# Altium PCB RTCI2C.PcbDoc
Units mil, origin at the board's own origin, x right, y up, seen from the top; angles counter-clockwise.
Board outline 1000 x 1125 mil, 2 copper layers (Top Layer, Bottom Layer), stack 61.855 mil thick; 14 components, 17 nets, 53 pads, 36 vias.
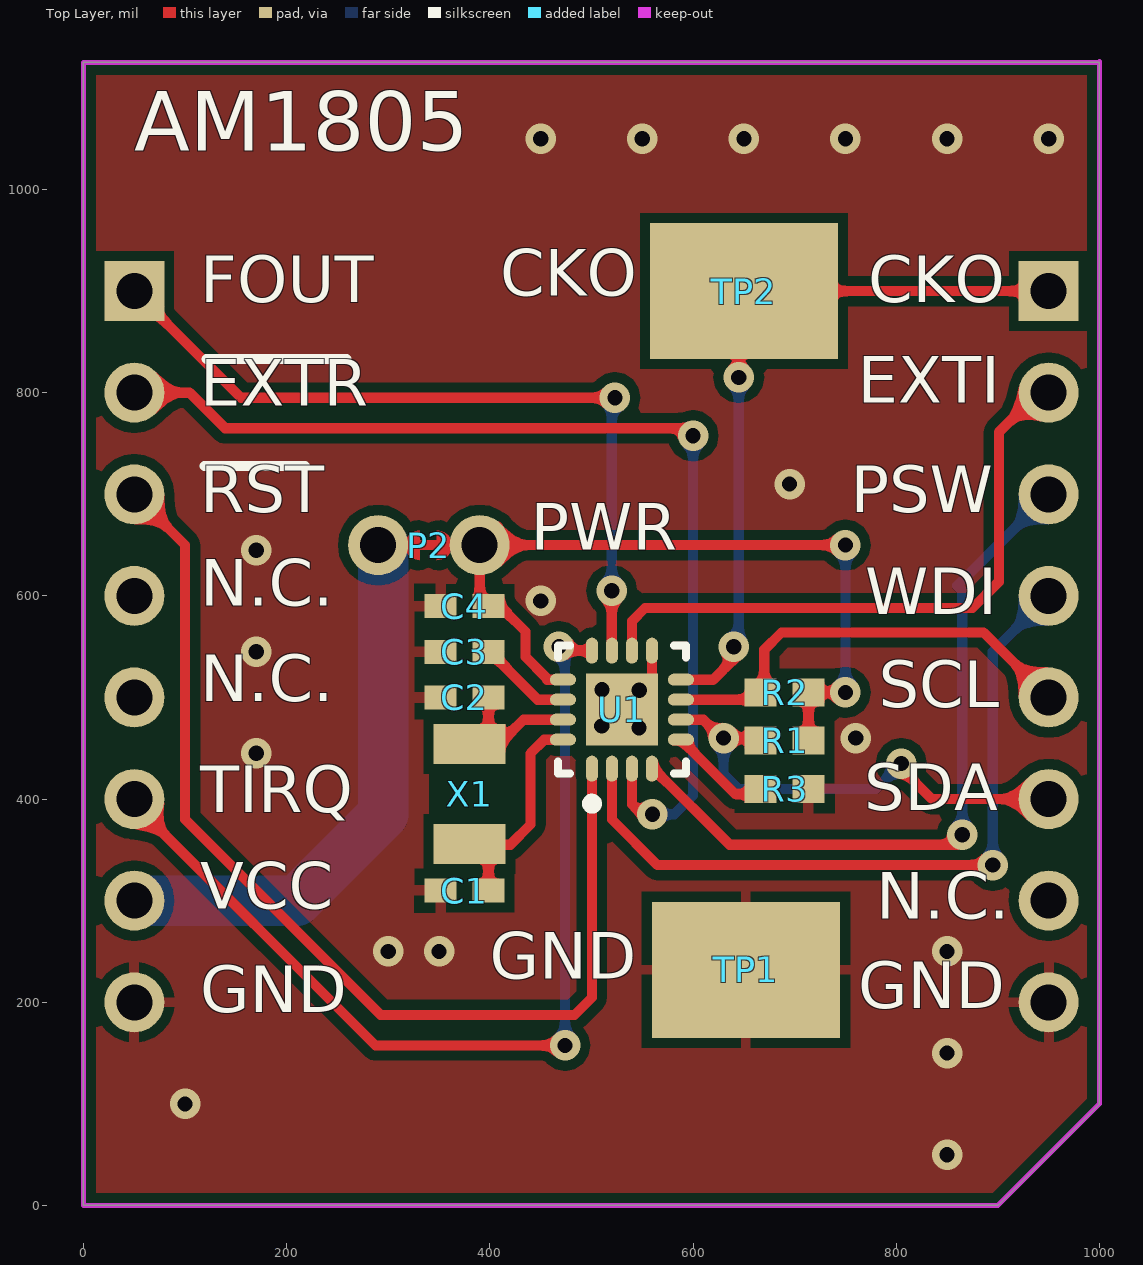
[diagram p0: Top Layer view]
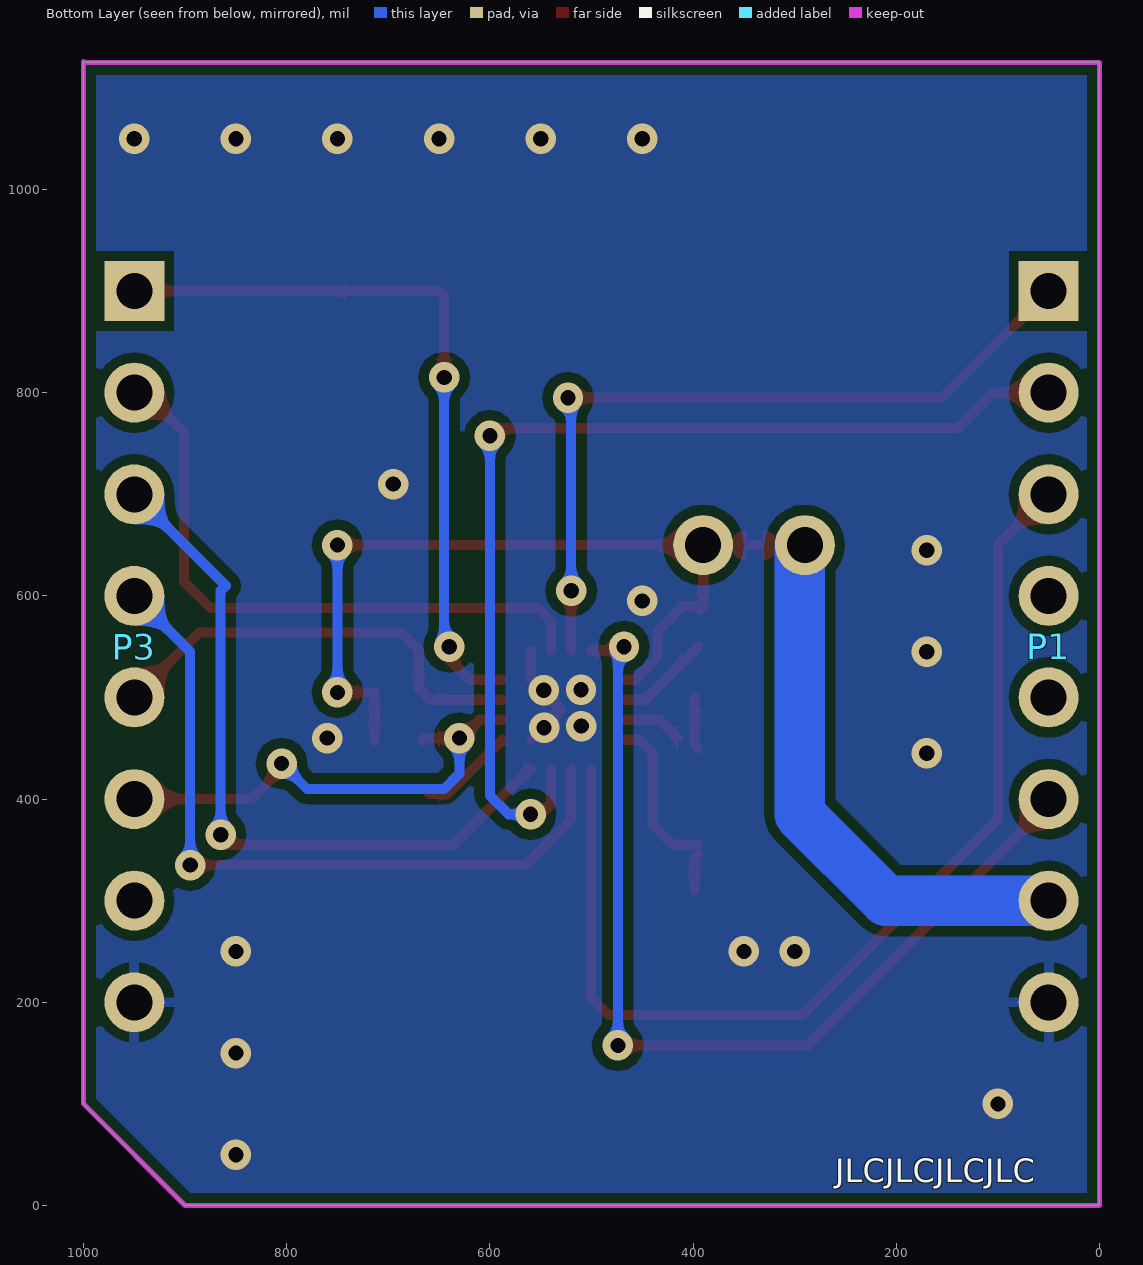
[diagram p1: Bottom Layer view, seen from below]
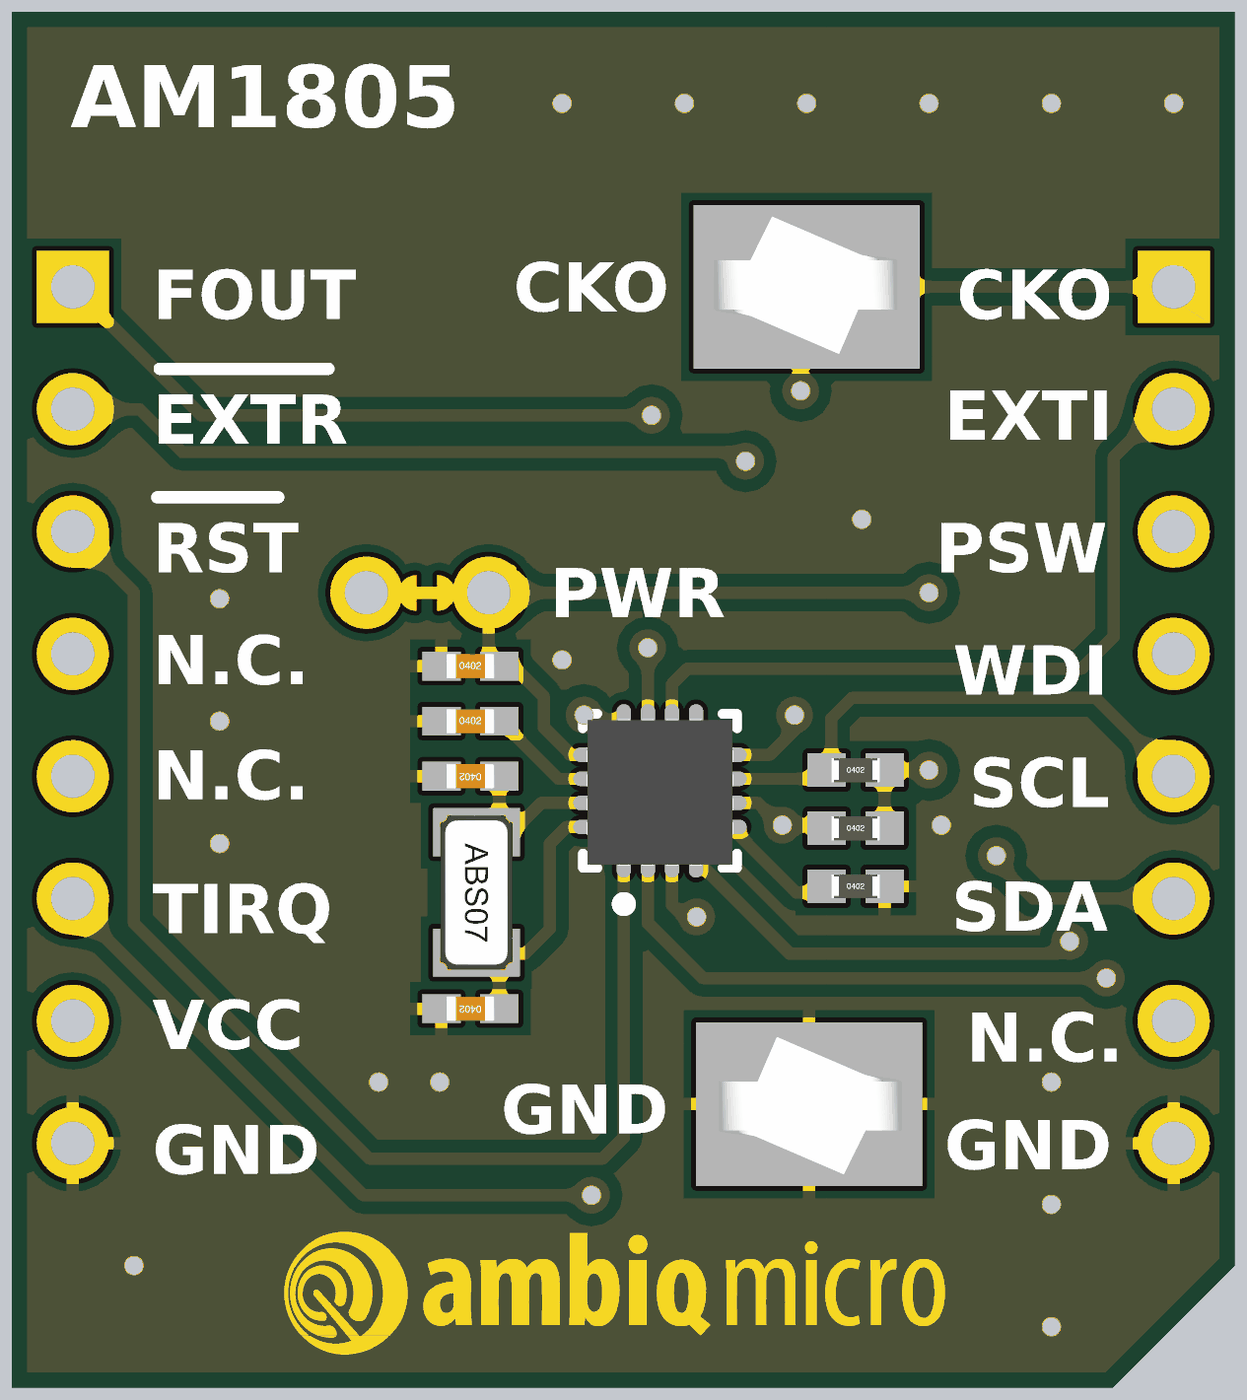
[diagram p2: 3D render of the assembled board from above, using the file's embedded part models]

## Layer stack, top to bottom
Top Solder: solder mask 0.4, Solder Resist, Dk 3.5
Top Layer: signal copper 1.4
Dielectric 1: dielectric 59.0551, FR-4, Dk 4.8
Bottom Layer: signal copper 1.4
Bottom Solder: solder mask 0.4, Solder Resist, Dk 3.5

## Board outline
0,0 900,0 1000,100 1000,1125 0,1125

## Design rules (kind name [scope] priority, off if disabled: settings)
Clearance [All] p1: gap=10 ignorepadtopadclearanceinfootprint=TRUE except(0: Arc-Hole Track-Hole SMDPad-Hole THPad-Hole Via-Hole Fill-Hole Poly-Hole Region-Hole Text-Hole; 8: Arc-Arc Arc-Track Arc-SMDPad Track-Track Track-SMDPad)
MinimumSolderMaskSliver [All] p1 off: minsoldermaskwidth=10
PolygonConnect PolygonConnect_1 [ISVIA] p1: connectstyle=Direct reliefconductorwidth=10 reliefentries=4 polygonreliefangle="90 Angle" airgapwidth=10
PolygonConnect [All] p2: connectstyle=Relief reliefconductorwidth=10 reliefentries=4 polygonreliefangle="90 Angle" airgapwidth=10
RoutingVias [All] p1: holewidth=15 width=30 viastyle="Through Hole" minholewidth=12 minwidth=24 maxholewidth=250 maxwidth=500
SilkToSolderMaskClearance [IsPad] p1 off: minsilkscreentomaskgap=10 clearancetoexposedcopper=TRUE
SolderMaskExpansion [All] p1: expansion=4
Width [All] p1: maxlimit=1000 minlimit=8 preferedwidth=10 minimp=50.000000 maximp=50.000000 favimp=50.000000
28 further rules are at their usual default settings.

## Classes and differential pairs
component class RTCI2C: C1 C2 C3 C4 P1 P2 P3 R1 R2 R3 TP1 TP2 U1

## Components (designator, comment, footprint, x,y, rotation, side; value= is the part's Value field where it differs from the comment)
C1 "1pF" CAPC1005N 375,310 r180 top
C2 "1pF" CAPC1005N 375,500 r180 top
C3 "47pF" CAPC1005N 375,545 r0 top
C4 "100nF" CAPC1005N 375,590 r0 top
P1 "Header 1X8" HEADER1X8 50,550 r270 bottom locked
P2 "SBS-HEADER" SBS-HEADER 340,650 r0 top net-tie
P3 "Header 1X8" HEADER1X8 950,550 r270 bottom locked
R1 "2K2" RESC1005N 690,457.5 r0 top
R2 "2K2" RESC1005N 690,505 r0 top
R3 "0R" RESC1005N 690,410 r0 top
TP1 "5016" 5016 652,232 r180 top
TP2 "5016" 5016 650,900 r0 top
U1 "AM1805" QFN50P300X300-16W4L 530,488 r90 top
X1 "ABS07W-32.768K" ABS07W 380,405 r270 top

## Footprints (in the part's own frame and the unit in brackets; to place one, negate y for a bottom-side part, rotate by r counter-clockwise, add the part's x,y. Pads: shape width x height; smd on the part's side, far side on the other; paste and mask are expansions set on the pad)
5016 [mm]
  rect 4.7x3.4 smd: 1(0,0)
  body extent -1.92,-1.4 1.89,1.46, height 2.3
ABS07W [mm]
  rect 1x1.8 smd: 1(-1.25,0) 2(1.25,0)
  body extent -1.61,-0.76 1.61,0.76, height 0.91
CAPC1005N [mm] "Chip Capacitor, Body 1.0x0.5mm, IPC Medium Density"
  rect 0.8x0.6 smd: 1(-0.6,0) 2(0.6,0)
  body extent -0.5,-0.26 0.5,0.26, height 0.51
HEADER1X8 [mm]
  rect 1.5x1.5 hole 0.9: 1(-8.89,0)
  round 1.5 hole 0.9: 2(-6.35,0) 3(-3.81,0) 4(-1.27,0) 5(1.27,0) 6(3.81,0) 7(6.35,0) 8(8.89,0)
  body extent -10.16,-1.27 10.16,1.27, height 8.38
QFN50P300X300-16W4L [mm] "QFN, 16-Leads, Body 3x3mm, Pitch 0.5mm, IPC High Density"
  oval 0.65x0.3 smd: 1(-1.475,0.75) 2(-1.475,0.25) 3(-1.475,-0.25) 4(-1.475,-0.75) 9(1.475,-0.75) 10(1.475,-0.25) 11(1.475,0.25) 12(1.475,0.75)
  oval 0.3x0.65 smd: 5(-0.75,-1.475) 6(-0.25,-1.475) 7(0.25,-1.475) 8(0.75,-1.475) 13(0.75,1.475) 14(0.25,1.475) 15(-0.25,1.475) 16(-0.75,1.475)
  rect 1.8x1.8 smd: 17(0,0)
  silkscreen extent -2.47,-1.6 1.6,1.6, body extent -1.55,-1.52 1.49,1.52, height 0.9
RESC1005N [mm] "Chip Resistor, Body 1.1x0.5mm, IPC Medium Density"
  rect 0.8x0.7 smd: 1(-0.6,0) 2(0.6,0)
  body extent -0.5,-0.25 0.5,0.25, height 0.3
SBS-HEADER [mm]
  round 1.5 hole 0.9: 1(-1.27,0) 2(1.27,0)
  Top Layer region: -0.225,-0.375 -0.388,-0.341 -0.52,-0.239 -0.594,-0.089 -0.594,0.078 -0.521,0.228 -0.389,0.33 -0.226,0.364 -0.226,0.364 -0.225,0.364
  Top Layer region: 0.2,0.364 0.363,0.33 0.495,0.228 0.569,0.078 0.569,-0.089 0.496,-0.239 0.364,-0.341 0.201,-0.376 0.201,-0.376 0.2,-0.375
  Top Layer lines w0.254: -1.27,0 1.27,0

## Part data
C1 C2 C3 C4: library part CAP_CHP, "Surface Mount Unpolarized Capacitor"
P1 P3: library part HDR1X8
R1 R2 R3: library part RES_CHP, "Surface Mount Resistor"
TP1 TP2: library part TP, "Test Point"
U1: "AM18X5 Real-Time Clock with Power / Management Family"
X1: library part ABS07W, "32.768KHZ IoT OPTIMIZED SMD CRYSTAL"

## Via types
v1: diameter 30, hole 15, Top Layer to Bottom Layer, tented both sides, 36 vias

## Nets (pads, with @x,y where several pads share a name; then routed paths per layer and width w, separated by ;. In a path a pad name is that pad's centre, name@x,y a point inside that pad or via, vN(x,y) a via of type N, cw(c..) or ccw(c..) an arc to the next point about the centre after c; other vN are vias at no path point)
3V3: P1.7 P2.1 | length 545.2
  Bottom Layer w50: P1.7 210,300 295,385 P2.1@295,650
CLKOUT/nIRQ4: P3.1 TP2.1 U1.8 | length 726.6
  Top Layer w10: U1.8 619.69,517.53 640,537.83 v1(640,550) ; v1(645,815) 645,895 TP2.1 P3.1
  Bottom Layer w10: v1(640,550) 645,555 v1(645,815)
EXTI: P3.2 U1.10 | length 618.5
  Top Layer w10: U1.10 539.84,575.16 552.68,588 875.03,588 901.01,613.99 901.01,761.01 940,800 P3.2
FOUT/nIRQ: P1.1 U1.11 | length 787
  Top Layer w10: P1.1 155,795 v1(523.11,795) ; U1.11 520,546.23 v1(520,605) 520,585.16 520.16,585
  Bottom Layer w10: v1(520,605) 520,791.89 v1(523.11,795)
GND: C1.2 C2.2 C3.1 C4.1 P1.8 P3.8 R3.2 TP1.1 U1.9 U1.17 | length 112.1
  Top Layer w10: U1.17@559.53,458.47 U1.17 559.53,517.53 U1.9
  other v1: 850,50 100,100 850,150 300,250 350,250 850,250 170,445 760,460 546.66,470.24 510,471.81 547,507 510.31,507.69 170,545 450,595 170,645 695,710 450,1050 550,1050 650,1050 750,1050 850,1050 950,1050
NetC1_1: C1.1 U1.16 X1.2 | length 197.3
  Top Layer w10: X1.2@395,345 398.62,341.38 C1.1 ; X1.2@395,355 420,355 440,375 440,445 453.47,458.47 U1.16
NetC2_1: C2.1 U1.15 X1.1 | length 116
  Top Layer w10: X1.1@395,450 398.62,453.62 C2.1 ; X1.1@414.91,460 433.07,478.16 U1.15
NetC3_2: C3.2 U1.14 | length 98.5
  Top Layer w10: C3.2@395,550 447.16,497.84 U1.14
NetR3_1: R3.1 U1.5 | length 94.1
  Top Layer w10: U1.5 641.54,405 R3.1@660,405
nEXTR: P1.2 U1.3 | length 1028.6
  Top Layer w10: P1.2 104.51,800 139.51,765 592.5,765 v1(600,757.5) ; U1.3 539.84,394.84 549.68,385 v1(560,385)
  Bottom Layer w10: v1(560,385) 581.53,385 600,403.47 v1(600,757.5)
nRST: P1.3 U1.1 | length 1053.3
  Top Layer w10: P1.3 100,650 100,380 292.5,187.5 483.3,187.5 500.47,204.67 U1.1
nTIRQ: P1.6 U1.12 | length 956.5
  Top Layer w10: P1.6 50,395 287.5,157.5 v1(474,157.5) ; v1(467.99,550.01) 471.93,546.07 U1.12
  Bottom Layer w10: v1(467.99,550.01) 474,544 v1(474,157.5)
PSW/nIRQ3: P3.3 U1.4 | length 715
  Top Layer w10: U1.4 561.07,429.93 636,355 855,355 v1(865,365)
  Bottom Layer w10: v1(865,365) 865,605 860,610 P3.3
SCL: P3.5 R2.1 U1.7 | length 438.3
  Top Layer w10: U1.7 659.22,497.84 R2.1 670,508.62 670,547 687,564 886,564 P3.5
SDA: P3.6 R1.1 U1.6 | length 479.4
  Top Layer w10: U1.6 610,478.16 626.53,461.63 v1@626.53,460 ; v1(630,460) 663.88,460 R1.1 ; v1@800,435 835,400 P3.6 P3.6@950,395.99
  Bottom Layer w10: v1(630,460) 630,425 645,410 780,410 v1(805,435)
VRTC: C4.2 P2.2 R1.2 R2.2 U1.13 | length 804.1
  Top Layer w10: P2.2 390,590 C4.2@394.31,585.69 ; P2.2@390,668 P2.2@397.46,668 ; C4.2 410,590 435,565 435,540 455,520 ; P2.2@408,650 P2.2@408,652 ; 456.51,517.53 U1.13 ; R1.2 R2.2 v1(749.99,505) ; v1(750,650) 410,650 P2.2@408,652 ; P2.2@397.46,668 P2.2@408,657.46 ; P2.2@397.46,668 408,668 P2.2@408,657.46 ; P2.2@408,652 P2.2@408,657.46
  Bottom Layer w10: v1(749.99,505) v1(750,650)
WDI: P3.4 U1.2 | length 731.3
  Top Layer w10: U1.2 520.16,379.84 565,335 v1(895,335)
  Bottom Layer w10: v1(895,335) 895,545 P3.4
pads on no net: P1.4 P1.5 P3.7

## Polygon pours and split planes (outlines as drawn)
GND on Bottom Layer "GND_L02_P006" (solid, remove dead copper, pour order 6): 0,0 900,0 1000,100 1000,1125 0,1125 -0.49,1124.51
GND on Top Layer "GND_L01_P002" (solid, remove dead copper, pour order 2): -0.49,-0.49 899.51,-0.49 999.51,99.51 999.51,1125.49 0.49,1125.49 -0.49,1124.51

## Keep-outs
Keep-Out Layer:
  lines w5: 999.02,1125 0,1125 0,0 900,0 1000,100 1000,1125.98

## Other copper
Top Layer:
  pour cut-out: 340,475 420,475 420,335 340,335

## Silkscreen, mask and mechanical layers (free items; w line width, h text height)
Top Overlay:
  lines w10: 119,728 218,728 ; 121,833 259,833
  text "AM1805" at 50,1018.96 h100
  text "CKO" at 410.1,880 h78.74
  text "FOUT" at 115,873.84 h78.74
  text "CKO" at 772.53,873.84 h78.74
  text "EXTI" at 762.15,775 h78.74
  text "EXTR" at 115,771.84 h78.74
  text "RST" at 115,666.84 h78.74
  text "PSW" at 755,666.84 h78.74
  text "PWR" at 440,630 h78.74
  text "N.C." at 115,575.16 h78.74
  text "WDI" at 769.52,566.84 h78.74
  text "N.C." at 115,481.12 h78.74
  text "SCL" at 782.68,475 h78.74
  text "SDA" at 768.27,373.68 h78.74
  text "TIRQ" at 115,371.84 h78.74
  text "VCC" at 115,277 h78.74
  text "N.C." at 780.39,266.84 h78.74
  text "GND" at 400,208 h78.74
  text "GND" at 762.43,178.84 h78.74
  text "GND" at 115.05,175 h78.74
Bottom Overlay:
  text "JLCJLCJLCJLC" at 260,15 h39.37
Top Solder:
  drawing of 6898 lines, arcs and shapes, not listed
Mechanical 1:
  lines w5: 1000,1125 0,1125 0,0 900,0 1000,100 1000,1125.98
